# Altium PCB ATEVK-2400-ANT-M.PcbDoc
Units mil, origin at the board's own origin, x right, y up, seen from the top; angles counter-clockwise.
Board outline 1701.38 x 629.92 mil, 2 copper layers (Top Layer, Bottom Layer); 5 components, 3 nets, 9 pads, 26 vias.
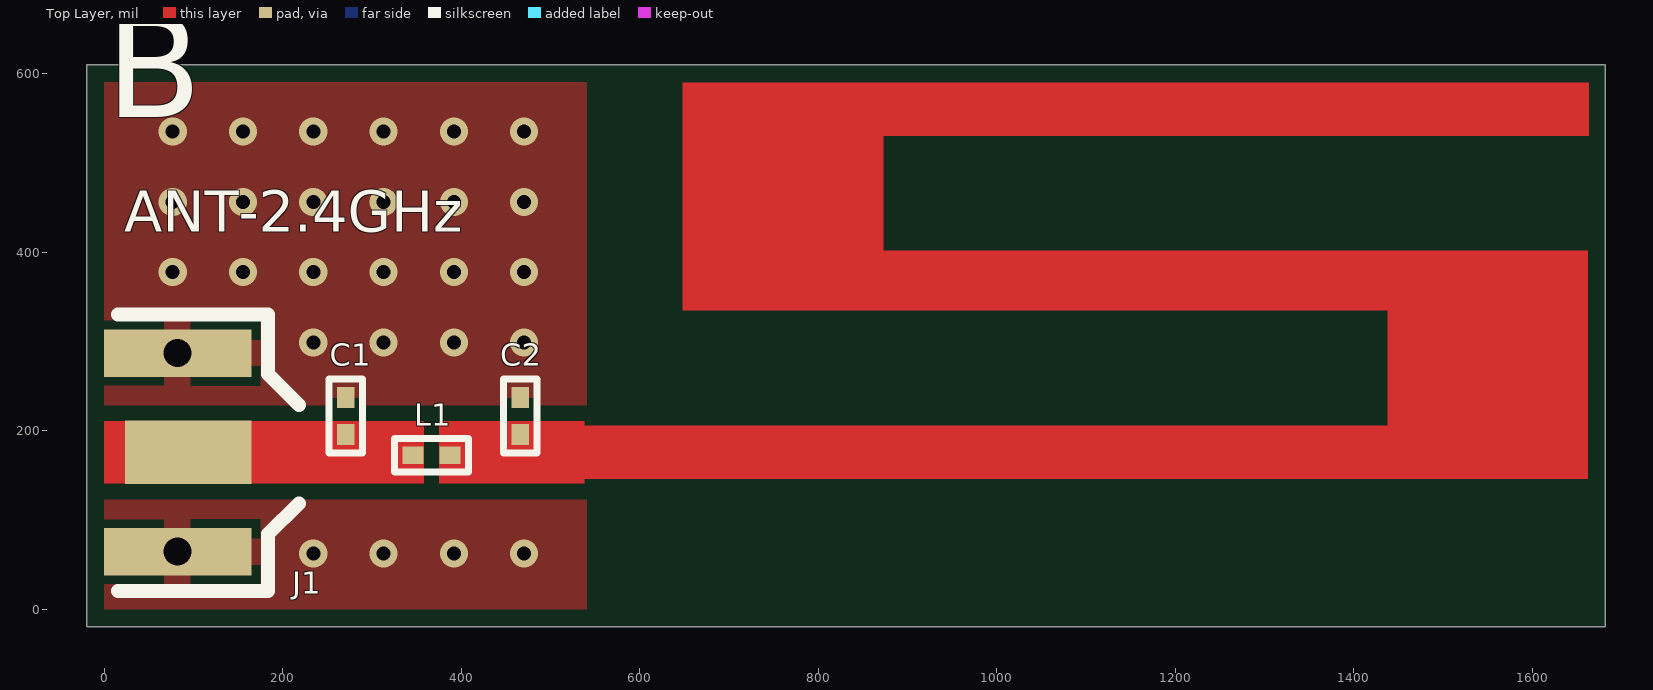
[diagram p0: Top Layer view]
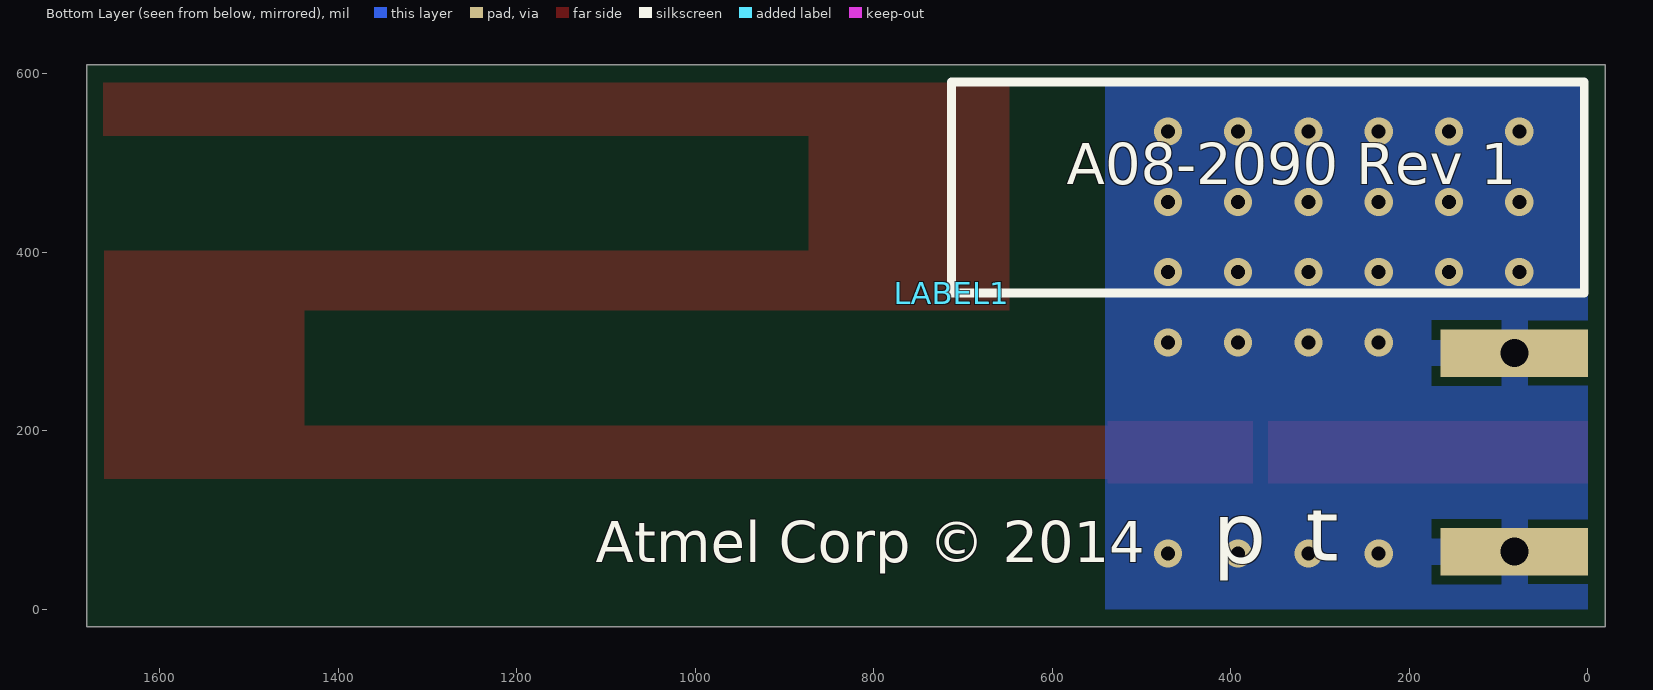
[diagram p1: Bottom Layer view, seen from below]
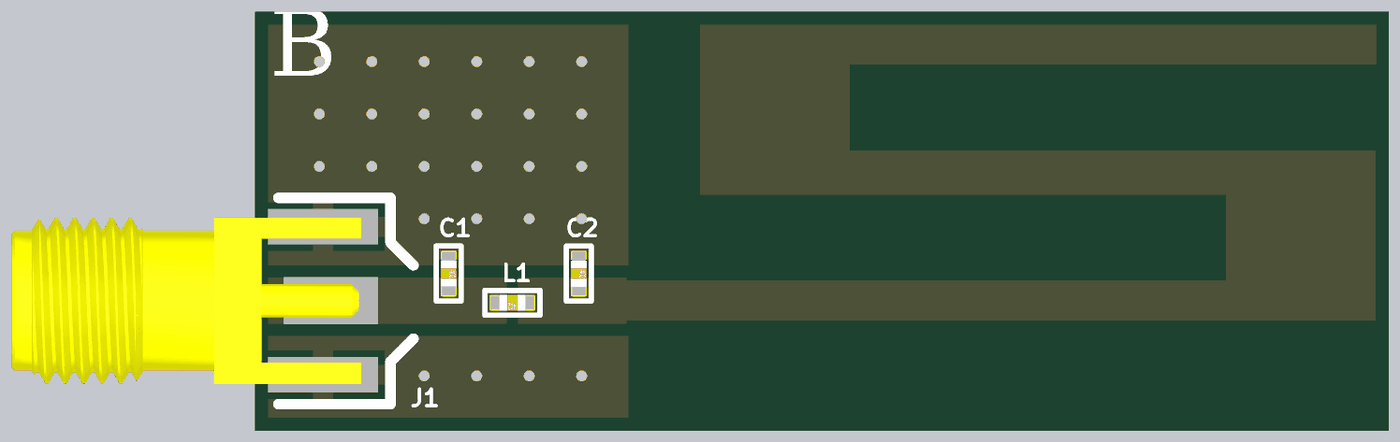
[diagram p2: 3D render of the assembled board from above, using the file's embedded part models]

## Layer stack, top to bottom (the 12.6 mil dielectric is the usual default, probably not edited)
Top Solder: solder mask 0.4, Solder Resist, Dk 3.5
Top Layer: signal copper 1.4
Dielectric1: core 12.6, FR-4, Dk 4.8
Bottom Layer: signal copper 1.4
Bottom Solder: solder mask 0.4, Solder Resist, Dk 3.5

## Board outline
-19.69,-19.68 -19.69,610.24 1681.69,610.24 1681.69,-19.68

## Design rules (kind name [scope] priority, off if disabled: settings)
Clearance [All] p1: gap=10
PolygonConnect PolygonConnect_Pad [(InPadClass('All Pads'))] p1: connectstyle=Relief reliefconductorwidth=30 reliefentries=4 polygonreliefangle="90 Angle" airgapwidth=10
PolygonConnect [All] p2: connectstyle=Direct reliefconductorwidth=10 reliefentries=4 polygonreliefangle="90 Angle" airgapwidth=10
RoutingVias [All] p1: holewidth=15.75 width=31.5 viastyle="Through Hole" minholewidth=15.75 minwidth=31.5 maxholewidth=15.75 maxwidth=31.5
SilkToSolderMaskClearance SilkscreenOverComponentPads [IsPad] p1: minsilkscreentomaskgap=10 clearancetoexposedcopper=TRUE
SolderMaskExpansion [All] p1: expansion=1.97
Width [All] p1: maxlimit=10 minlimit=10 preferedwidth=10
28 further rules are at their usual default settings.

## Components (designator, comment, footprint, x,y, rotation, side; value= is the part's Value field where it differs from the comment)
C1 "CAP-NONPOL" AP1-00038 270.78,195.98 r180 top
C2 "CAP-NONPOL" AP1-00038 466.16,195.87 r180 top
J1 "Board Edge Mounting" AP8-00443 94.02,175.87 r0 top
L1 "New part to be used in \"ATEVK-2400-ANT-M\"" AP1-00038 345.92,172.68 r90 top
LABEL1 "PCBA_LABEL" AP8-00317 712.6,354.33 r180 bottom

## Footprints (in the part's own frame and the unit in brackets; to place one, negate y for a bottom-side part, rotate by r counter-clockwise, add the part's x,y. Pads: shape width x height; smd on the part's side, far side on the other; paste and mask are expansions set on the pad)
AP1-00038 [mm] "Generic pad 0402, spacing 0.45mm"
  rect 0.5x0.6 smd: 1(0,0) 2(0,-1.05)
  silkscreen extent -0.48,-1.58 0.48,0.53, body extent -0.3,-1.02 0.3,-0.03, height 0.2
AP8-00317 [mil] "Placement area for 18x6mm sticker"
  silkscreen extent 0,0 709,236
AP8-00443 [mm] "SMA card edge mount 1.6mm substrate"
  rect 3.6x1.8 smd paste-0.9 mask+0: 1(0,0)
  rect 4.2x1.35 hole 0.8 paste-0.3 mask+0: 2(-0.3,-2.825) 2.1(-0.3,2.825)
  silkscreen extent -2,-3.95 3.15,3.92, body extent -12.17,-3.18 1.16,3.18, height 3.71

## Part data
C1 C2: library part A01-0015, "Ceramic capacitor, SMD 0402, NP0, 50V, +/-5%"
J1: library part A08-1047, "End Launch Jack Receptacle, Round Contact (de21535)"
L1: library part A03-0193, "RF Inductor, 8.2nH, +/-5%, 0.4Ohm, 250mA, 0402"
LABEL1: library part A09-0611, "PCBA identification label PP Top White Gloss"

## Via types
v1: diameter 31.5, hole 15.75, Top Layer to Bottom Layer, tented both sides, 26 vias

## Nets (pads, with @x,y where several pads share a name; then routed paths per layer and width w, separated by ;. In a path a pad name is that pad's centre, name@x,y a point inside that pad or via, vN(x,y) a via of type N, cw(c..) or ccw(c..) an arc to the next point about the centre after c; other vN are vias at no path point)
GND: C1.2 C2.2 J1.2 J1.2.1
  other v1: 234.22,62.76 312.96,62.76 391.7,62.76 470.44,62.76 234.22,298.98 312.96,298.98 391.7,298.98 470.44,298.98 76.74,377.72 155.48,377.72 234.22,377.72 312.96,377.72 391.7,377.72 470.44,377.72 76.74,456.46 155.48,456.46 234.22,456.46 312.96,456.46 391.7,456.46 470.44,456.46 76.74,535.2 155.48,535.2 234.22,535.2 312.96,535.2 391.7,535.2 470.44,535.2
NetC1_1: C1.1 J1.1 L1.1
NetC2_1: C2.1 L1.2

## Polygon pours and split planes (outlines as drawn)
GND on Top Layer "Top Layer-No Net 1" (solid, remove dead copper, pour order 5): 0,590.55 0,228.87 540.52,228.87 540.52,590.55
GND on Top Layer "Top Layer-No Net 1" (solid, remove dead copper, pour order 6): 0,0 0,122.55 540.52,122.55 540.52,0
GND on Bottom Layer "Top Layer-No Net" (solid, remove dead copper, pour order 4): 0,590.1 0,0 540.52,0 540.52,590.55

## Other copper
Top Layer:
  rectangle net NetC1_1: 0,140.87 358,210.87
  rectangle net NetC2_1: 375,140.87 538,210.87
  rectangle net NetC2_1: 531.31,146.32 1583.27,206.16
  rectangle net NetC2_1: 647.8,334.9 1583.27,401.83
  rectangle net NetC2_1: 647.8,530.57 1663.54,590.41
  rectangle net NetC2_1: 647.8,335.32 872.8,588.8
  rectangle net NetC2_1: 1437.36,146.32 1662.36,401.83

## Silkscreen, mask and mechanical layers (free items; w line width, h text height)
Top Overlay:
  text "B" at 1.97,513.78 h196.85
  text "ANT-2.4GHz" at 22.25,407.79 h78.74
Bottom Overlay:
  text "A08-2090 Rev 1" at 583.51,461.24 h78.74
  text "Atmel Corp © 2014" at 1111.42,37.58 h78.74
  text "t" at 316,31.87 h118.11
  text "p" at 420,28.87 h118.11
Top Paste:
  rectangle: 23.16,140.45 164.87,211.32
  rectangle: -0.39,260.43 164.86,313.68
  rectangle: -0.39,38.29 164.86,91.54
Bottom Paste:
  rectangle: -0.39,38.29 164.86,91.54
  rectangle: -0.39,260.43 164.86,313.68
Mechanical 1:
  the board outline again, w10
Mechanical 4:
  drawing of 169 lines, arcs and shapes, not listed
  text "( SEE NOTE 1A )" at -1541.17,1665.94 h70
  text "SOLDER LEVEL" at -2547.21,1663.97 h70
  text "COPPER PLATE" at -2547.21,1563.97 h70
  text "35 um" at -1552.21,1513.97 h70
  text "LAYER 1" at -3857.21,1463.97 h70
  text "COPPER FOIL" at -2547.21,1463.97 h70
  text "}" at -1692.21,1458.97 h175
  text "Core" at -2522.22,665.59 h70
  text "( SEE NOTE 2A )" at -1527.46,664.13 h70
  text "1530um" at -1916.72,661.37 h70
  text "( SEE NOTE 3A )" at -4400.98,629.44 h70
  text "LAYER 2" at -3857.21,-186.03 h70
  text "COPPER FOIL" at -2547.21,-186.03 h70
  text "35 um" at -1552.21,-236.03 h70
  text "COPPER PLATE" at -2547.21,-286.03 h70
  text "}" at -1692.21,-291.03 h175
  text "( SEE NOTE 1A )" at -1536.11,-381.3 h70
  text "SOLDER LEVEL" at -2547.21,-386.03 h70
  text "NOTE :" at -3258.97,-538.74 h70
  text "1A:  SURFACE PROTECTION: Chemical Gold" at -3069.86,-695.27 h70
  text "2A:  DIELECTRIC FR4 (S1000)" at -3081.49,-845.34 h70
  text "3A:  TOTAL THICKESS TO BE DEFINED BY MANUFACTURER" at -3082.99,-1006.79 h70
  text "WITH RESPECT TO STANDARD FINISHING" at -2815.53,-1155.04 h70
  text "THE BOARD MUST BE RoHS COMPLIANT" at -3087.89,-1358.44 h70
  text "DETAIL A ( CROSS-SECTION )" at -3786.44,-1864.55 h120
  text "SCALE = NONE" at -3031.44,-2044.55 h70
Drill Drawing:
  text ".legend" at 457.48,-1212.73 h60

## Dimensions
-19.69,-19.68 to 1681.69,-19.68 on Mechanical 13
1681.69,-19.68 to 1681.69,610.24 on Mechanical 13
